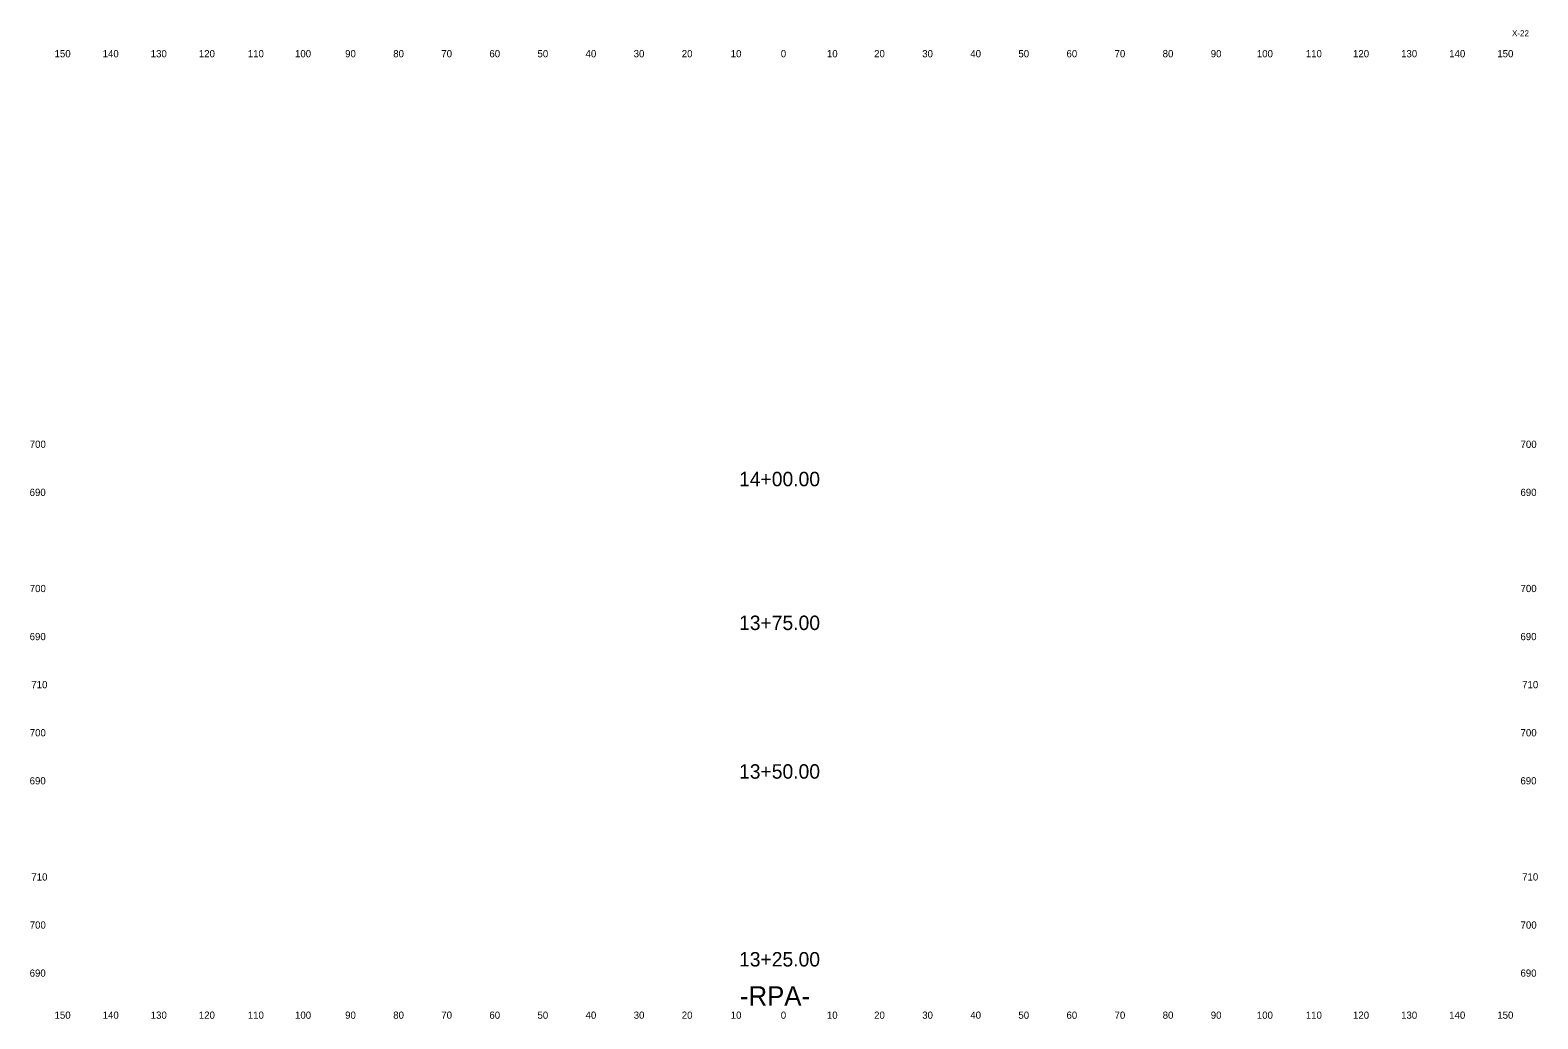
# Model space of a CAD drawing. Extents: x 3 to 317, y 1 to 867.
# Drawn here: x 3.4 to 316.9, y 661.2 to 866.9 of the extents above; entities that cross this region are included whole.
import ezdxf

# ---------------------------------------------------------------- set-up
doc = ezdxf.new("R2010")
doc.units = 0
for name, color, linetype in [('Prop XS Alignment Label', 7, 'Continuous'), ('Prop XS Elevation Labels', 7, 'Continuous'), ('Prop XS Offset Labels', 7, 'Continuous'), ('Prop XS Sheet Number', 7, 'Continuous'), ('Prop XS Station Labels', 7, 'Continuous')]:
    doc.layers.add(name, color=color, linetype=linetype)

msp = doc.modelspace()

# ---------------------------------------------------------------- texts
at = {"layer": 'Prop XS Alignment Label'}
msp.add_text('-RPA-', height=4, dxfattribs=at).set_placement((150.97, 664))
at = {"layer": 'Prop XS Elevation Labels'}
for s, p in [('700', (3.28, 780)), ('700', (313.28, 780)), ('690', (3.26, 770)), ('690', (313.26, 770)), ('700', (3.28, 750)), ('700', (313.28, 750)), ('690', (3.26, 740)), ('690', (313.26, 740)), ('710', (3.61, 730)), ('710', (313.61, 730)), ('700', (3.28, 720)), ('700', (313.28, 720)), ('690', (3.26, 710)), ('690', (313.26, 710)), ('710', (3.61, 690)), ('710', (313.61, 690)), ('700', (3.28, 680)), ('700', (313.28, 680)), ('690', (3.26, 670)), ('690', (313.26, 670))]:
    msp.add_text(s, height=1.5, dxfattribs=at).set_placement(p)
at = {"layer": 'Prop XS Offset Labels'}
for s, p in [('150', (8.44, 861.25)), ('140', (18.44, 861.25)), ('130', (28.44, 861.25)), ('120', (38.44, 861.25)), ('110', (48.62, 861.25)), ('100', (58.44, 861.25)), ('90', (68.86, 861.25)), ('80', (78.86, 861.25)), ('70', (88.86, 861.25)), ('60', (98.86, 861.25)), ('50', (108.86, 861.25)), ('40', (118.86, 861.25)), ('30', (128.86, 861.25)), ('20', (138.86, 861.25)), ('10', (149.04, 861.25)), ('0', (159.45, 861.25)), ('10', (169.04, 861.25)), ('20', (178.86, 861.25)), ('30', (188.86, 861.25)), ('40', (198.86, 861.25)), ('50', (208.86, 861.25)), ('60', (218.86, 861.25)), ('70', (228.86, 861.25)), ('80', (238.86, 861.25)), ('90', (248.86, 861.25)), ('100', (258.44, 861.25)), ('110', (268.62, 861.25)), ('120', (278.44, 861.25)), ('130', (288.44, 861.25)), ('140', (298.44, 861.25)), ('150', (308.44, 861.25)), ('150', (8.44, 661.25)), ('140', (18.44, 661.25)), ('130', (28.44, 661.25)), ('120', (38.44, 661.25)), ('110', (48.62, 661.25)), ('100', (58.44, 661.25)), ('90', (68.86, 661.25)), ('80', (78.86, 661.25)), ('70', (88.86, 661.25)), ('60', (98.86, 661.25)), ('50', (108.86, 661.25)), ('40', (118.86, 661.25)), ('30', (128.86, 661.25)), ('20', (138.86, 661.25)), ('10', (149.04, 661.25)), ('0', (159.45, 661.25)), ('10', (169.04, 661.25)), ('20', (178.86, 661.25)), ('30', (188.86, 661.25)), ('40', (198.86, 661.25)), ('50', (208.86, 661.25)), ('60', (218.86, 661.25)), ('70', (228.86, 661.25)), ('80', (238.86, 661.25)), ('90', (248.86, 661.25)), ('100', (258.44, 661.25)), ('110', (268.62, 661.25)), ('120', (278.44, 661.25)), ('130', (288.44, 661.25)), ('140', (298.44, 661.25)), ('150', (308.44, 661.25))]:
    msp.add_text(s, height=1.5, dxfattribs=at).set_placement(p)
at = {"layer": 'Prop XS Sheet Number'}
msp.add_text('X-22', height=1.25, dxfattribs=at).set_placement((311.5, 865.63))
at = {"layer": 'Prop XS Station Labels'}
for s, p in [('14+00.00', (150.77, 772.02)), ('13+75.00', (150.77, 742.11)), ('13+50.00', (150.77, 711.19)), ('13+25.00', (150.77, 672.12))]:
    msp.add_text(s, height=3, dxfattribs=at).set_placement(p)

doc.saveas('drawing.dxf')
